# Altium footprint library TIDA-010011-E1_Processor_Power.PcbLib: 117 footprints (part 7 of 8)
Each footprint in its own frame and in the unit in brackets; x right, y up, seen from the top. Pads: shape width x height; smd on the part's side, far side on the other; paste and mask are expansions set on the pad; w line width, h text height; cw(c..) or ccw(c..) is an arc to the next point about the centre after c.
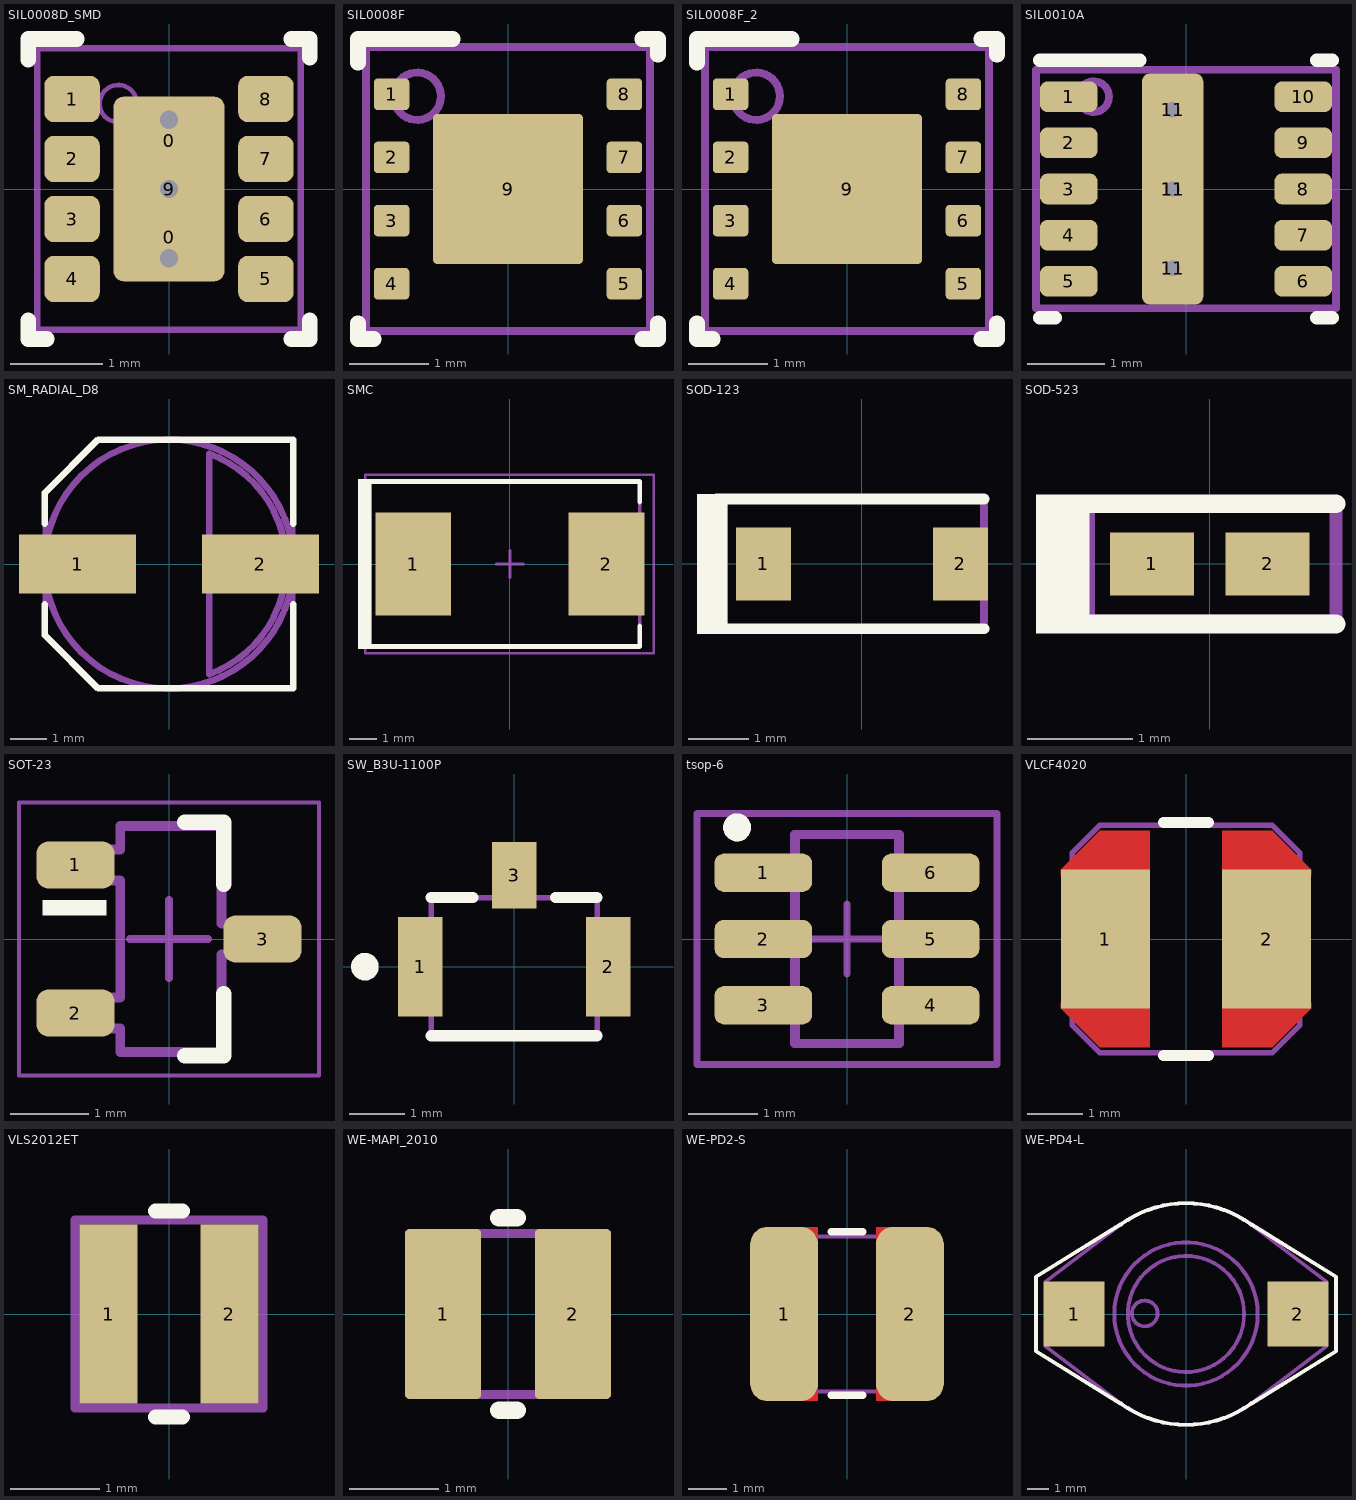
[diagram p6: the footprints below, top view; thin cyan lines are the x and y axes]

## SIL0008D_SMD [mm] "SIP, 8-Leads, Body 2.8x3.0mm, Pitch 0.65mm, Thermal Pad 1.9x1.1mm"
height 1.53
pads (11):
  rrect50% 1.04x0.85 on Top Paste: 0(0,-0.525) 0(0,0.525)
  rrect40% 0.6x0.5 smd paste-0.05 mask-0.05: 1(-1.05,0.975) 2(-1.05,0.325) 3(-1.05,-0.325) 4(-1.05,-0.975) 5(1.05,-0.975) 6(1.05,-0.325) 7(1.05,0.325) 8(1.05,0.975)
  rrect17% 1.2x2 smd paste-0.6 mask-0.05: 9(0,0)
via 0,-0.75 diameter 0.5 hole 0.2
via 0,0.75 diameter 0.5 hole 0.2
via 0,0 diameter 0.5 hole 0.2
Top Overlay:
  lines w0.17: -1.525,-1.425 -1.525,-1.625 -1.325,-1.625 ; -1.525,1.4 -1.525,1.625 -1,1.625 ; 1.325,-1.625 1.525,-1.625 1.525,-1.425 ; 1.325,1.625 1.525,1.625 1.525,1.425
Mechanical 5:
  circle w0.05: c-0.55,0.925 r0.202
  lines w0.07: -1.425,-1.525 1.425,-1.525 1.425,1.525 -1.425,1.525 -1.425,-1.525
  text ".Designator" at 0.533,-0.628 h0.51
3D body: height 1.53, standoff 1.53, extent -0.751,0.724 -0.349,1.126
3D body "SIL0008D.stp": height 1.53, standoff 0, extent -1.4,-1.5 1.4,1.5

## SIL0008F [mm]
height 1.75
pads (9):
  rrect25% 0.45x0.4 smd: 1(-1.475,1.2) 2(-1.475,0.4) 3(-1.475,-0.4) 4(-1.475,-1.2) 5(1.475,-1.2) 6(1.475,-0.4) 7(1.475,0.4) 8(1.475,1.2)
  rrect5% 1.9x1.9 smd paste-0.95: 9(0,0)
Top Overlay:
  lines w0.2: -1.9,-1.7 -1.9,-1.9 -1.7,-1.9 ; -1.9,1.6 -1.9,1.9 -0.7,1.9 ; 1.7,-1.9 1.9,-1.9 1.9,-1.7 ; 1.7,1.9 1.9,1.9 1.9,1.7
Top Paste:
  rectangle: 0.1,0.1 0.86,0.86
  region: -0.1,0.86 -0.86,0.86 -0.86,0.1 -0.1,0.1
  region: -0.1,-0.1 -0.86,-0.1 -0.86,-0.86 -0.1,-0.86
  rectangle: 0.1,-0.86 0.86,-0.1
Mechanical 5:
  circle w0.1: c-1.15,1.175 r0.3
  lines w0.1: -1.8,-1.8 1.8,-1.8 1.8,1.8 -1.8,1.8 -1.8,-1.8
  text ".Designator" at 0.013,0.432 h0.51
3D body "SIL0008F.stp": height 1.66, standoff 0, extent -1.76,-1.75 1.74,1.75

## SIL0008F_2 [mm]
pads (9):
  rrect25% 0.45x0.4 smd: 1(-1.475,1.2) 2(-1.475,0.4) 3(-1.475,-0.4) 4(-1.475,-1.2) 5(1.475,-1.2) 6(1.475,-0.4) 7(1.475,0.4) 8(1.475,1.2)
  rrect5% 1.9x1.9 smd paste-0.95: 9(0,0)
Top Overlay:
  lines w0.2: -1.9,-1.7 -1.9,-1.9 -1.7,-1.9 ; -1.9,1.6 -1.9,1.9 -0.7,1.9 ; 1.7,-1.9 1.9,-1.9 1.9,-1.7 ; 1.7,1.9 1.9,1.9 1.9,1.7
Top Paste:
  rectangle: 0.1,0.1 0.86,0.86
  region: -0.1,0.86 -0.86,0.86 -0.86,0.1 -0.1,0.1
  region: -0.1,-0.1 -0.86,-0.1 -0.86,-0.86 -0.1,-0.86
  rectangle: 0.1,-0.86 0.86,-0.1
Mechanical 5:
  circle w0.1: c-1.15,1.175 r0.3
  lines w0.1: -1.8,-1.8 1.8,-1.8 1.8,1.8 -1.8,1.8 -1.8,-1.8
  text ".Designator" at -0.151,0.438 h0.51
3D body "SIL0008F.stp": height 1.66, standoff 0, extent -1.76,-1.75 1.74,1.75

## SIL0010A [mm] "MicoSiP, TI recommended land pattern"
height 1.578
pads (14):
  rrect50% 0.75x0.4 smd paste-0.05 mask-0.05: 1(-1.525,1.2) 2(-1.525,0.6) 3(-1.525,0) 4(-1.525,-0.6) 5(-1.525,-1.2) 6(1.525,-1.2) 7(1.525,-0.6) 8(1.525,0) 9(1.525,0.6) 10(1.525,1.2)
  rrect50% 0.7x0.833 on Top Paste: 11(-0.175,-1.03) 11(-0.175,0) 11(-0.175,1.03)
  rrect25% 0.8x3 smd paste-0.5 mask-0.05: 11(-0.175,0)
via -0.175,-1.03 diameter 0.5 hole 0.2
via -0.175,1.03 diameter 0.5 hole 0.2
via -0.175,0 diameter 0.5 hole 0.2
Top Overlay:
  lines w0.178: -1.9,-1.675 -1.7,-1.675 ; -1.9,1.675 -0.6,1.675 ; 1.7,-1.675 1.9,-1.675 ; 1.7,1.675 1.9,1.675
Mechanical 5:
  circle w0.1: c-1.2,1.2 r0.2
  lines w0.1: -1.95,-1.55 1.95,-1.55 1.95,1.55 -1.95,1.55 -1.95,-1.55
  text ".Designator" at 0.539,-2.2 h0.51
3D body "SIL0010A.stp": height 1.49, standoff 0, extent -1.9,-1.5 1.9,1.5

## SM_RADIAL_D8 [mm] "6.3 x 7.7mm:  Panasonic D8"
height 8
pads (2):
  rect 3.2x1.6 smd: 1(-2.5,0) 2(2.5,0)
Top Overlay:
  lines w0.178: -3.398,-1.099 -3.398,-1.942 -1.94,-3.4 3.4,-3.4 3.4,-1.1 ; -3.398,1.099 -3.398,1.942 -1.94,3.4 3.4,3.4 3.4,1.1
Mechanical 5:
  lines w0.127: -3.398,-1.942 -1.94,-3.4 3.4,-3.4 3.4,3.4 -1.94,3.4 -3.398,1.942 -3.398,-1.942
  text ".Designator" at 0.364,0.358 h0.51
Mechanical 13:
  circle w0.178: c0,0 r3.4
  lines w0.178: 1.097,-3.014 ccw(c0,0) 1.097,3.014 1.097,-3.014
3D body: height 0.6, standoff 0, extent -3.398,-3.401 3.401,3.401
3D body: height 8.01, standoff 7.9, extent 1.097,-3.015 3.208,3.015
3D body: height 8, standoff 0.6, extent -3.399,-3.399 3.399,3.399

## SMC [mil] "Molded Diode, 2-Leads, Body 6.9x5.8mm, IPC Medium Density, based on OnSemi component dimensions and land patterns"
height 94.88
pads (2):
  rect 110x150 smd: 1(-140.49,0) 2(140.49,0)
Top Overlay:
  rectangle: -221.02,-123.49 -201.02,123.51
  lines w7: -210,-120 189,-120 189,-90.25 ; -210,120 189,120 189,90.25
Mechanical 5:
  rectangle: -221.02,-123.49 -201.02,123.51
  lines w5: -210,-120 189,-120 189,120 -210,120
  text ".Designator" at -85,-20 h20
Mechanical 15:
  lines w3.94: -19.69,0 19.68,0 ; 0,-19.68 0,19.68 ; -210.46,-129.92 -210.46,129.92 209.38,129.92 209.38,-129.92 -210.46,-129.92
3D body "SMC_nominal.stp": height 91.35, standoff 0.6, extent -156.49,-116.13 156.5,116.15

## SOD-123 [mm] "On Semi recommended land pattern"
height 1.35
pads (2):
  rect 0.915x1.22 smd: 1(-1.637,0) 2(1.637,0)
Top Overlay:
  rectangle: -2.742,-1.169 -2.234,1.168
  lines w0.178: -2.413,-1.079 2.032,-1.079 ; -2.413,1.079 2.032,1.079
Mechanical 5:
  rectangle: -2.742,-1.169 -2.234,1.168
  lines w0.127: -2.413,-1.079 2.032,-1.079 2.032,1.079 -2.413,1.079
  text ".Designator" at -0.787,-0.203 h0.51
3D body "SOD-123.stp": height 1.35, standoff 0, extent -1.932,-0.9 1.932,0.9

## SOD-523 [mm] "NXP Semiconductor recommended land pattern, nominal STEP model"
height 0.7
pads (2):
  rect 0.8x0.6 smd paste-0.05: 1(-0.55,0) 2(0.55,0)
Top Overlay:
  rectangle: -1.652,-0.661 -1.144,0.66
  lines w0.178: -1.475,-0.572 0,-0.572 1.2,-0.572 ; -1.475,0.572 0,0.572 1.2,0.572
Mechanical 5:
  rectangle: -1.601,-0.635 -1.093,0.635
  lines w0.127: -1.475,-0.546 0,-0.546 1.2,-0.546 1.2,0.546 0,0.559 -1.475,0.559
  text ".Designator" at -0.533,-0.203 h0.51
3D body "SOD-523F.stp": height 0.72, standoff 0.02, extent -0.8,-0.399 0.8,0.399

## SOT-23 [mm] "SOT23, 3-Leads, Body 2.9x1.3mm, Pitch 0.95mm, Lead Span 2.5mm, IPC Medium Density"
height 1.1
pads (3):
  rrect50% 1x0.6 smd: 1(-1.2,0.95) 2(-1.2,-0.95) 3(1.2,0)
Top Overlay:
  rectangle: -1.625,0.3 -0.8,0.5
  lines w0.2: 0.2,-1.5 0.7,-1.5 0.7,-0.7 ; 0.2,1.5 0.7,1.5 0.7,0.7
Mechanical 5:
  lines w0.127: -1.16,-1.15 -0.625,-1.15 -0.625,-1.45 0.675,-1.45 0.675,-0.2 1.21,-0.2 1.21,0.2 0.675,0.2 0.675,1.45 -0.625,1.45 -0.625,1.15 -1.16,1.15 -1.16,0.75 -0.625,0.75 -0.625,-0.75 -1.16,-0.75 -1.16,-1.15
  text ".Designator" at 0.235,-0.33 h0.51
Mechanical 15:
  lines w0.05: -1.925,-1.75 -1.925,1.75 1.925,1.75 1.925,-1.75 -1.925,-1.75
  lines w0.1: -0.5,0 0.5,0 ; 0,-0.5 0,0.5
3D body "SW3dPS-sot-3p290x130ll237h100.STEP": height 1, standoff 0, extent -1.16,-1.45 1.21,1.45

## SW_B3U-1100P [mm] "SMD, 3-Leads, Body 3x2.5mm"
height 1.75
pads (3):
  rect 0.8x1.8 smd: 1(-1.7,0) 2(1.7,0)
  rect 0.8x1.2 smd: 3(0,1.65)
Top Overlay:
  circle w0.25: c-2.7,0 r0.125
  lines w0.2: -1.5,-1.25 1.5,-1.25 ; -1.5,1.25 -0.75,1.25 ; 0.75,1.25 1.5,1.25
Mechanical 5:
  lines w0.1: -1.5,-0.7 -2,-0.7 -2,0.7 -1.5,0.7 ; -0.25,1.25 -0.25,1.9 0.25,1.9 0.25,1.25 ; -0.25,1.55 0.25,1.55 ; 1.5,-0.7 2,-0.7 2,0.7 1.5,0.7 ; -1.5,-1.25 -1.5,1.25 1.5,1.25 1.5,-1.25 -1.5,-1.25
  text ".Designator" at 0.389,0.262 h0.51
3D body: height 1.6, standoff 0, extent -2,-1.25 2,1.9

## tsop-6 [mm] "TSOP, 6-Leads, Body 3.1x1.7mm (max), Pitch 0.95mm, IPC Medium Density"
height 1.1
pads (6):
  rrect50% 1.4x0.55 smd: 1(-1.2,0.95) 2(-1.2,0) 3(-1.2,-0.95) 4(1.2,-0.95) 5(1.2,0) 6(1.2,0.95)
Top Overlay:
  circle w0.2: c-1.575,1.6 r0.1
Mechanical 5:
  circle w0.2: c-1.575,1.6 r0.1
  lines w0.127: -0.75,-1.14 -0.75,-0.76 ; -0.75,-1.14 -1.155,-1.14 -1.275,-1.14 -1.375,-1.14 -1.375,-0.76 -1.275,-0.76 -1.155,-0.76 -0.75,-0.76 ; -0.75,-1.14 -0.75,-1.5 -0.736,-1.5 ; -0.75,-0.76 -0.75,-0.19 ; -0.75,-0.19 -0.75,0.19 ; -0.75,-0.19 -1.155,-0.19 -1.275,-0.19 -1.375,-0.19 -1.375,0.19 -1.275,0.19 -1.155,0.19 -0.75,0.19 ; -0.75,0.19 -0.75,0.76 ; -0.75,0.76 -0.75,1.14 ; -0.75,0.76 -1.155,0.76 -1.275,0.76 -1.375,0.76 -1.375,1.14 -1.275,1.14 -1.155,1.14 -0.75,1.14 ; -0.75,1.14 -0.75,1.5 -0.736,1.5 ; -0.736,-1.5 -0.736,1.5 ; -0.736,-1.5 0.736,-1.5 ; -0.736,1.5 0.736,1.5 ; 0.736,-1.5 0.736,1.5 ; 0.736,-1.5 0.75,-1.5 0.75,-1.14 ; 0.736,1.5 0.75,1.5 0.75,1.14 ; 0.75,-1.14 0.75,-0.76 ; 0.75,-1.14 1.155,-1.14 1.275,-1.14 1.375,-1.14 1.375,-0.76 1.275,-0.76 1.155,-0.76 0.75,-0.76 ; 0.75,-0.76 0.75,-0.19 ; 0.75,-0.19 0.75,0.19 ; 0.75,-0.19 1.155,-0.19 1.275,-0.19 1.375,-0.19 1.375,0.19 1.275,0.19 1.155,0.19 0.75,0.19 ; 0.75,0.19 0.75,0.76 ; 0.75,0.76 1.155,0.76 1.275,0.76 1.375,0.76 1.375,1.14 1.275,1.14 1.155,1.14 0.75,1.14 ; 0.75,0.76 0.75,1.14
  text ".Designator" at -0.229,0.762 h0.51
Mechanical 15:
  lines w0.1: -0.5,0 0.5,0 ; 0,-0.5 0,0.5 ; -2.15,-1.8 2.15,-1.8 2.15,1.8 -2.15,1.8 -2.15,-1.8
3D body "TSOP6.stp": height 1.05, standoff 0, extent -1.375,-1.5 1.375,1.5

## VLCF4020 [mm] "TDK"
height 2
pads (2):
  rect 1.6x2.5 smd: 1(-1.45,0) 2(1.45,0)
Top Layer:
  region: -0.65,-1.95 -1.55,-1.95 -2.25,-1.25 -2.25,-1.15 -0.65,-1.15
  region: -0.65,1.95 -1.55,1.95 -2.25,1.25 -2.25,1.15 -0.65,1.15
  region: 0.65,1.95 1.55,1.95 2.25,1.25 2.25,1.15 0.65,1.15
  region: 0.65,-1.95 1.55,-1.95 2.25,-1.25 2.25,-1.15 0.65,-1.15
Top Overlay:
  lines w0.2: -0.4,-2.1 0.4,-2.1 ; -0.4,2.1 0.4,2.1
Mechanical 5:
  lines w0.1: -2.05,-1.55 -2.05,1.55 -1.55,2.05 1.55,2.05 2.05,1.55 2.05,-1.55 1.55,-2.05 -1.55,-2.05 -2.05,-1.55
  text ".Designator" at -0.25,0.622 h0.51
3D body: height 2, standoff 0, extent -2.051,-0.001 2.051,2.051
3D body: height 2, standoff 0, extent -2.051,-2.051 2.051,0.001

## VLS2012ET [mm] "TDK"
height 1.2
pads (2):
  rect 0.65x2 smd: 1(-0.675,0) 2(0.675,0)
Top Overlay:
  lines w0.165: -0.15,-1.15 0.15,-1.15 ; -0.15,1.15 0.15,1.15
Mechanical 5:
  lines w0.1: -1.05,-1.05 -1.05,1.05 1.05,1.05 1.05,-1.05 -1.05,-1.05
  text ".Designator" at 0.311,-0.406 h0.51
3D body: height 1.2, standoff 0, extent -1.049,-1.049 1.049,1.049

## WE-MAPI_2010 [mm] "WURTH"
height 1
pads (2):
  rrect12% 0.85x1.9 smd: 1(-0.725,0) 2(0.725,0)
Top Overlay:
  lines w0.2: -0.1,-1.075 0.1,-1.075 ; -0.1,1.075 0.1,1.075
Mechanical 5:
  lines w0.1: -1.1,-0.9 1.1,-0.9 1.1,0.9 -1.1,0.9 -1.1,-0.9
  text ".Designator" at 0.761,0.42 h0.51
3D body: height 1, standoff 0, extent -1.099,-0.899 1.099,0.899

## WE-PD2-S [mm] "WURTH"
height 3.5
pads (2):
  rrect50% 1.75x4.5 smd: 1(-1.625,0) 2(1.625,0)
Top Layer:
  rectangle: -1.375,-2.25 -0.75,2.25
  region: 1.375,2.25 0.75,2.25 0.75,-2.25 1.375,-2.25
Top Overlay:
  lines w0.2: -0.4,-2.1 0.4,-2.1 ; -0.4,2.125 0.4,2.125
Mechanical 5:
  lines w0.1: -1.894,-0.182 -2.008,-0.182 -2.05,-0.182 cw(c-2.05,0) -2.05,0.182 -2.008,0.182 -1.894,0.182 ; 1.894,-0.182 2.051,-0.182 ccw(c2.05,0) 2.05,0.182 ; 1.894,0.182 2.049,0.182 ; -2.214,-0.398 cw(c-0.025,0) -2.214,0.398 ; -2.214,-0.398 ccw(c-0.025,0) -1,-2 1,-2 ccw(c0.025,0) 2.214,-0.398 ; -2.214,-0.398 ccw(c-2.25,0) -2.214,0.398 ; -2.214,0.398 cw(c-0.025,0) -1,2 1,2 cw(c0.025,0) 2.214,0.398 ; 2.049,0.182 2.05,0.182 ; 2.214,-0.398 ccw(c0.025,0) 2.214,0.398 ; 2.214,-0.398 cw(c2.25,0) 2.214,0.398
  text ".Designator" at -0.66,-0.229 h0.51
3D body "WE-PD2-S.stp": height 3.18, standoff 0, extent -2.25,-2 2.25,2

## WE-PD4-L [mm] "Wurth Elektronick recommended land pattern"
height 5.3
pads (2):
  rect 2.8x3 smd: 1(-5.15,0) 2(5.15,0)
Top Overlay:
  lines w0.178: -6.906,-1.71 -3,-4.125 ccw(c0,0) 0,-5.1 ccw(c0,0) 3,-4.125 6.906,-1.71 6.9,-1.71 6.9,0 6.9,1.71 6.906,1.71 3,4.125 ccw(c0,0) 0,5.1 ccw(c0,0) -3,4.125 -6.906,1.71 -6.9,1.71 -6.9,0 -6.9,-1.71 -6.906,-1.71
Mechanical 5:
  text ".Designator" at -0.559,-0.229 h0.51
Mechanical 13:
  circle w0.178: c-1.9,0.025 r0.593
  circle w0.178: c0,0 r3.3
  circle w0.178: c0,0 r2.676
  lines w0.178: -6.45,-1.5 -3,-4.125 ccw(c0,0) 0,-5.1 ccw(c0,0) 3,-4.125 6.45,-1.5 6.45,0 6.45,1.5 3,4.125 ccw(c0,0) 0,5.1 ccw(c0,0) -3,4.125 -6.45,1.5 -6.45,0 -6.45,-1.5
3D body: height 5.3, standoff 5.3, extent -2.492,-0.567 -1.308,0.617
3D body: height 2, standoff 1.5, extent -3.299,-3.299 3.299,3.299
3D body: height 1.5, standoff 0, extent -6.451,-5.101 6.451,5.101
3D body: height 4.8, standoff 2, extent -2.676,-2.676 2.676,2.676
3D body: height 5.3, standoff 4.8, extent -3.299,-3.299 3.299,3.299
